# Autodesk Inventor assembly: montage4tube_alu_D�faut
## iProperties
Created: 2011-01
Part Number: montage4tube_alu_D�faut
Document SubType Name: Assembly
Designer: eric
Mass: 291.278 g
Surface Area: 2742.8 cm^2
Volume: 291.278 cm^3
Density: 1 g/cm^3
Author: eric
